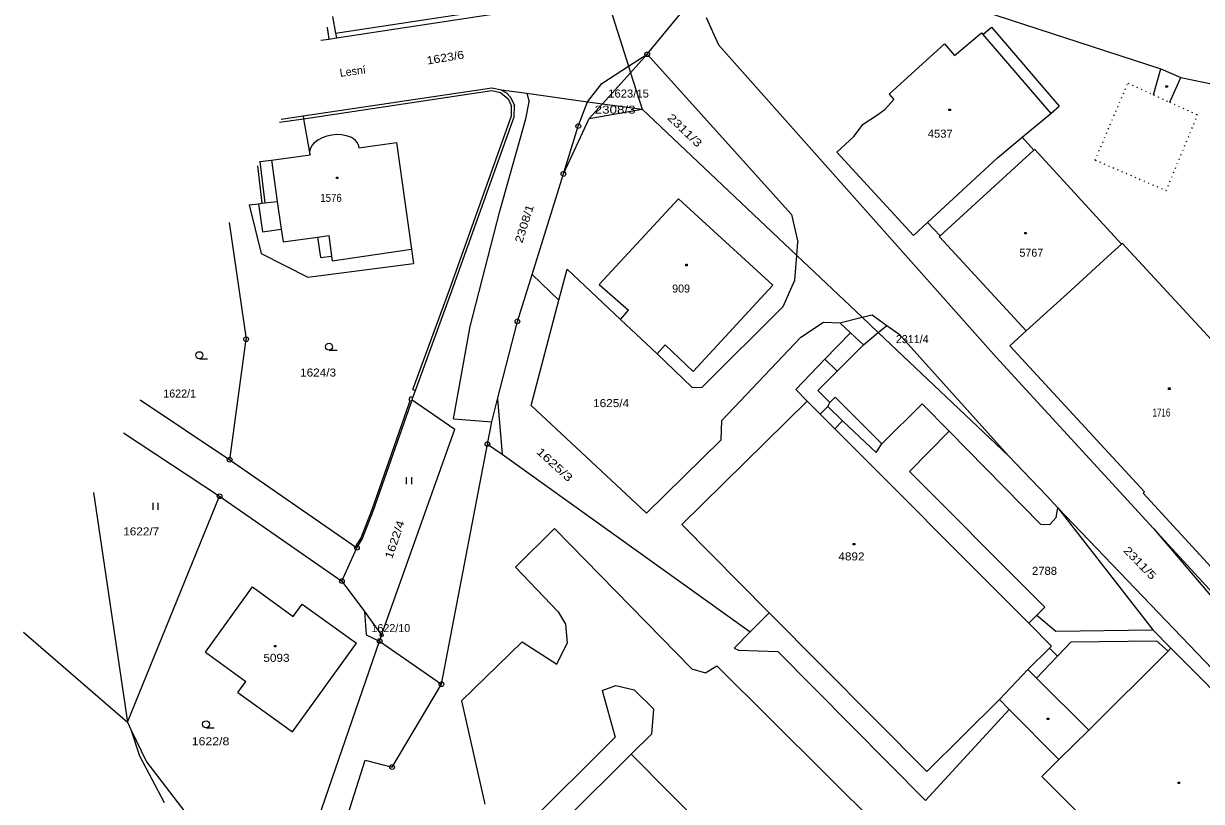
# Model space of a CAD drawing. Extents: x -630464 to -630140, y -1004543 to -1004208.
# Drawn here: x -630464 to -630338.9, y -1004428.9 to -1004346.3 of the extents above; entities that cross this region are included whole.
import ezdxf

# ---------------------------------------------------------------- set-up
doc = ezdxf.new("R2010")
doc.units = 0
doc.header["$LTSCALE"] = 0.34
doc.linetypes.add('DOTTED', pattern=[1.5, 0.3, -1.2])
for name, color, linetype, lineweight in [('1', 7, 'Continuous', 13), ('2', 7, 'Continuous', 13), ('23', 7, 'Continuous', 13), ('25', 7, 'Continuous', 13), ('28', 7, 'Continuous', 13)]:
    doc.layers.add(name, color=color, linetype=linetype, lineweight=lineweight)
for name, color, linetype in [('14', 7, 'Continuous'), ('15', 7, 'Continuous'), ('38', 7, 'Continuous')]:
    doc.layers.add(name, color=color, linetype=linetype)

msp = doc.modelspace()

# ---------------------------------------------------------------- linework, layer by layer
at = {"layer": '1'}
for p, q in [((-630397.75, -1004349.57), (-630393.43, -1004344.32)), ((-630365.09, -1004344), (-630343.21, -1004351.12)), ((-630431.183, -1004345.566), (-630430.87, -1004347.35)), ((-630431.753, -1004346.701), (-630431.75, -1004346.72)), ((-630431.75, -1004346.72), (-630431.57, -1004347.96)), ((-630432.449, -1004348.088), (-630431.57, -1004347.96)), ((-630430.87, -1004347.35), (-630430.78, -1004347.84)), ((-630343.97, -1004353.88), (-630343.21, -1004351.12)), ((-630434.31, -1004356.13), (-630414.28, -1004353.14)), ((-630413.24, -1004353.35), (-630410.54, -1004353.72)), ((-630372.04, -1004353.83), (-630371.55, -1004354.38)), ((-630411.9, -1004356.21), (-630411.87, -1004355.02)), ((-630354.89, -1004355.86), (-630353.98, -1004355.08)), ((-630436.658, -1004356.468), (-630434.31, -1004356.13)), ((-630357.92, -1004358.39), (-630354.89, -1004355.86)), ((-630360.55, -1004360.58), (-630357.92, -1004358.39)), ((-630377.61, -1004359.98), (-630369.46, -1004368.81)), ((-630367.97, -1004367.43), (-630360.55, -1004360.58)), ((-630439.154, -1004361.437), (-630438.69, -1004365.4)), ((-630442.168, -1004367.438), (-630440.37, -1004379.84)), ((-630369.46, -1004368.81), (-630367.97, -1004367.43)), ((-630366.62, -1004368.87), (-630367.97, -1004367.43)), ((-630381.87, -1004370.96), (-630381.75, -1004369.54)), ((-630366.72, -1004368.97), (-630366.62, -1004368.87)), ((-630357.49, -1004378.95), (-630366.72, -1004368.97)), ((-630353.16, -1004375.01), (-630348.44, -1004370.69)), ((-630347.29, -1004369.64), (-630333.06, -1004385.05)), ((-630433.83, -1004373.26), (-630422.58, -1004371.78)), ((-630409.99, -1004372.95), (-630407.15, -1004375.7)), ((-630391.95, -1004384.98), (-630383.32, -1004376.35)), ((-630381.44, -1004379.61), (-630379.02, -1004378.03)), ((-630379.02, -1004378.03), (-630377.29, -1004378.09)), ((-630378.89, -1004381.97), (-630376.15, -1004379.15)), ((-630376.15, -1004379.15), (-630374.77, -1004380.43)), ((-630442.12, -1004392.63), (-630440.37, -1004379.84)), ((-630377.58, -1004383.24), (-630374.77, -1004380.43)), ((-630359.24, -1004380.55), (-630344.92, -1004396.04)), ((-630381.98, -1004385.16), (-630378.89, -1004381.97)), ((-630379.64, -1004385.29), (-630377.58, -1004383.24)), ((-630393.02, -1004384.92), (-630391.95, -1004384.98)), ((-630381.98, -1004385.16), (-630380.76, -1004386.4)), ((-630379.64, -1004385.29), (-630378.37, -1004386.56)), ((-630451.637, -1004386.291), (-630442.12, -1004392.63)), ((-630413.67, -1004386.22), (-630413.18, -1004392.06)), ((-630410.08, -1004386.88), (-630397.83, -1004398.3)), ((-630394.08, -1004399.52), (-630380.76, -1004386.4)), ((-630372.84, -1004390.95), (-630368.56, -1004386.69)), ((-630368.56, -1004386.69), (-630365.69, -1004389.61)), ((-630397.83, -1004398.3), (-630389.92, -1004390.51)), ((-630413.18, -1004392.06), (-630386.82, -1004410.92)), ((-630369.91, -1004393.89), (-630356.72, -1004407.09)), ((-630456.571, -1004396.114), (-630452.97, -1004420.51)), ((-630452.97, -1004420.51), (-630443.2, -1004396.51)), ((-630443.2, -1004396.51), (-630430.19, -1004405.52)), ((-630345.07, -1004396.18), (-630344.92, -1004396.04)), ((-630345.07, -1004396.18), (-630336.65, -1004405.35)), ((-630354.15, -1004397.75), (-630317.27, -1004436.17)), ((-630394.08, -1004399.52), (-630384.8, -1004408.88)), ((-630444.68, -1004413.09), (-630439.71, -1004406.15)), ((-630356.72, -1004407.09), (-630355.52, -1004408.3)), ((-630356.38, -1004409.15), (-630355.52, -1004408.3)), ((-630427.81, -1004408.76), (-630425.98, -1004411.26)), ((-630356.38, -1004409.15), (-630354.36, -1004410.83)), ((-630464.017, -1004410.94), (-630452.97, -1004420.51)), ((-630426.2, -1004411.89), (-630419.62, -1004416.48)), ((-630444.68, -1004413.09), (-630440.39, -1004416.19)), ((-630441.24, -1004417.36), (-630440.39, -1004416.19)), ((-630452.61, -1004421.27), (-630450.96, -1004424.73)), ((-630355.83, -1004426.26), (-630354.04, -1004424.47)), ((-630450.96, -1004424.73), (-630446.52, -1004430.49))]:
    msp.add_line(p, q, dxfattribs=at)
at = {"layer": '1', "linetype": 'DOTTED'}
for p, q in [((-630350.17, -1004360.81), (-630346.69, -1004352.63)), ((-630346.69, -1004352.63), (-630343.97, -1004353.88)), ((-630342.25, -1004354.67), (-630339.29, -1004356.02)), ((-630342.62, -1004364.05), (-630339.29, -1004356.02)), ((-630350.17, -1004360.81), (-630342.62, -1004364.05))]:
    msp.add_line(p, q, dxfattribs=at)
at = {"layer": '1'}
for points in [[(-630431.57, -1004347.96), (-630430.78, -1004347.84), (-630408.36, -1004344.42), (-630404.14, -1004336.97), (-630403.55, -1004338.86), (-630399.75, -1004350.85), (-630399.53, -1004351.54)], [(-630391.49, -1004345.66), (-630390.2, -1004348.57), (-630360.7, -1004381.74)], [(-630372.04, -1004353.83), (-630366.19, -1004348.48), (-630365.1, -1004349.71), (-630362.23, -1004347.31), (-630362.1, -1004347.46), (-630361.19, -1004346.68), (-630353.98, -1004355.08)], [(-630399.53, -1004351.54), (-630397.75, -1004349.57), (-630382.44, -1004366.59), (-630381.75, -1004369.54)], [(-630402.51, -1004354.83), (-630399.53, -1004351.54), (-630398.31, -1004355.4)], [(-630342.25, -1004354.67), (-630341.06, -1004352.03), (-630321.38, -1004356.13)], [(-630414.28, -1004353.14), (-630413.24, -1004353.35), (-630412.7, -1004353.67), (-630412.3, -1004354.13), (-630411.87, -1004355.02)], [(-630410.54, -1004353.72), (-630404.12, -1004354.61), (-630402.51, -1004354.83)], [(-630377.61, -1004359.98), (-630375.82, -1004358.31), (-630374.83, -1004356.99), (-630373.29, -1004356.01), (-630372.49, -1004355.4), (-630371.55, -1004354.38)], [(-630409.99, -1004372.95), (-630406.66, -1004362.29), (-630403.94, -1004356.41), (-630398.31, -1004355.4), (-630381.87, -1004370.96)], [(-630403.94, -1004356.41), (-630402.51, -1004354.83), (-630398.31, -1004355.4)], [(-630434.31, -1004356.13), (-630434.26, -1004356.43), (-630433.63, -1004360)], [(-630422.74, -1004386.27), (-630422.65, -1004386.02), (-630422.39, -1004385.27), (-630418.5, -1004374.7), (-630411.9, -1004356.21)], [(-630428.46, -1004359.16), (-630428.4, -1004359.5), (-630424.41, -1004358.93), (-630422.79, -1004370.29), (-630422.58, -1004371.78)], [(-630347.39, -1004369.73), (-630356.59, -1004359.69), (-630356.69, -1004359.77), (-630357.92, -1004358.39)], [(-630440.04, -1004365.58), (-630439.04, -1004365.45), (-630438.69, -1004365.4)], [(-630440.04, -1004365.58), (-630438.76, -1004370.72), (-630433.83, -1004373.26)], [(-630348.44, -1004370.69), (-630347.39, -1004369.73), (-630347.29, -1004369.64)], [(-630383.32, -1004376.35), (-630382.08, -1004373.55), (-630381.87, -1004370.96), (-630374.93, -1004377.51)], [(-630413.67, -1004386.22), (-630411.55, -1004377.94), (-630409.99, -1004372.95)], [(-630410.08, -1004386.88), (-630407.15, -1004375.7), (-630406.28, -1004372.4), (-630400.61, -1004377.74), (-630396.71, -1004381.39), (-630393.02, -1004384.92)], [(-630359.24, -1004380.55), (-630357.49, -1004378.95), (-630353.16, -1004375.01)], [(-630377.29, -1004378.09), (-630374.93, -1004377.51), (-630373.22, -1004379.14), (-630359.37, -1004392.23), (-630355.39, -1004396.39), (-630354.15, -1004397.75)], [(-630374.93, -1004377.51), (-630373.85, -1004377.25), (-630372.29, -1004378.37), (-630370.98, -1004379.31), (-630359.37, -1004392.23)], [(-630389.92, -1004390.51), (-630389.85, -1004388.46), (-630381.44, -1004379.61)], [(-630360.7, -1004381.74), (-630343.98, -1004399.94), (-630338.03, -1004406.42), (-630333.23, -1004411.18), (-630324.32, -1004420.02), (-630324.04, -1004420.28), (-630303.74, -1004439.53), (-630293.73, -1004449.03), (-630288.99, -1004453.52), (-630254.82, -1004485.91)], [(-630430.19, -1004405.52), (-630428.6, -1004401.98), (-630428.05, -1004401.07), (-630426.83, -1004397.99), (-630422.89, -1004386.7), (-630422.74, -1004386.27), (-630418.21, -1004389.39)], [(-630378.37, -1004386.56), (-630377.79, -1004385.98), (-630372.84, -1004390.95)], [(-630426.2, -1004411.89), (-630425.98, -1004411.26), (-630418.21, -1004389.39)], [(-630369.91, -1004393.89), (-630365.69, -1004389.61), (-630355.97, -1004399.47)], [(-630419.62, -1004416.48), (-630414.74, -1004390.98), (-630413.18, -1004392.06)], [(-630442.12, -1004392.63), (-630428.74, -1004401.88), (-630428.6, -1004401.98)], [(-630355.97, -1004399.47), (-630355, -1004399.5), (-630354.31, -1004398.78), (-630354.15, -1004397.75), (-630344.06, -1004410.7)], [(-630430.19, -1004405.52), (-630427.81, -1004408.76), (-630427.62, -1004411.24), (-630426.2, -1004411.89)], [(-630439.71, -1004406.15), (-630435.37, -1004409.29), (-630434.42, -1004407.97), (-630428.66, -1004412.13)], [(-630388.51, -1004412.66), (-630386.82, -1004410.92), (-630384.8, -1004408.88)], [(-630354.36, -1004410.83), (-630344.06, -1004410.7), (-630342.12, -1004412.66), (-630334.14, -1004420.69), (-630328.57, -1004426.3)], [(-630453.27, -1004473.63), (-630434.6, -1004435.86), (-630434.12, -1004434.9), (-630426.2, -1004411.89)], [(-630441.24, -1004417.36), (-630435.45, -1004421.54), (-630428.66, -1004412.13)], [(-630388.51, -1004412.66), (-630388.08, -1004412.86), (-630383.88, -1004413), (-630368.18, -1004428.81)], [(-630450.67, -1004475.56), (-630431.15, -1004435.38), (-630427.72, -1004424.53), (-630424.86, -1004425.28), (-630419.62, -1004416.48)], [(-630368.18, -1004428.81), (-630359.29, -1004419.16), (-630354.04, -1004424.47)], [(-630452.97, -1004420.51), (-630452.61, -1004421.27), (-630451.7, -1004424.09), (-630449.09, -1004429.04)], [(-630414.09, -1004438.44), (-630413.36, -1004437.72), (-630399.48, -1004423.9), (-630390.92, -1004432.51)], [(-630355.83, -1004426.26), (-630342.18, -1004439.92), (-630329.96, -1004427.73), (-630329.26, -1004426.99), (-630328.44, -1004427.8), (-630326.87, -1004429.52), (-630322.01, -1004434.84)]]:
    msp.add_lwpolyline(points, dxfattribs=at)
for centre, radius, start, end in [((-630430.724, -1004361.937), 3.827, 66.37961, 130.12116), ((-630432.222, -1004360.033), 1.408, 133.41474, 178.66028), ((-630429.79, -1004359.76), 1.459, 24.2739, 65.7261)]:
    msp.add_arc(centre, radius, start, end, dxfattribs=at)
at = {"layer": '2'}
for p, q in [((-630430.87, -1004347.35), (-630408.67, -1004343.96)), ((-630431.763, -1004346.722), (-630431.75, -1004346.72)), ((-630362.1, -1004347.46), (-630354.89, -1004355.86)), ((-630399.75, -1004350.85), (-630397.75, -1004349.57)), ((-630402.59, -1004352.67), (-630399.75, -1004350.85)), ((-630343.21, -1004351.12), (-630341.06, -1004352.03)), ((-630434.26, -1004356.43), (-630414.27, -1004353.44)), ((-630414.27, -1004353.44), (-630413.36, -1004353.63)), ((-630413.36, -1004353.63), (-630412.55, -1004354.3)), ((-630412.55, -1004354.3), (-630412.17, -1004355.08)), ((-630410.54, -1004353.72), (-630410.29, -1004354.61)), ((-630412.19, -1004356.1), (-630412.17, -1004355.08)), ((-630410.67, -1004356.44), (-630410.29, -1004354.61)), ((-630436.824, -1004356.798), (-630434.26, -1004356.43)), ((-630418.78, -1004374.6), (-630412.19, -1004356.1)), ((-630413.41, -1004366.24), (-630410.67, -1004356.44)), ((-630406.66, -1004362.29), (-630405.08, -1004357.21)), ((-630438.9, -1004360.98), (-630437.68, -1004360.82)), ((-630437.68, -1004360.82), (-630433.58, -1004360.27)), ((-630437.68, -1004360.82), (-630437.06, -1004365.2)), ((-630433.63, -1004360), (-630433.58, -1004360.27)), ((-630366.62, -1004368.87), (-630356.69, -1004359.77)), ((-630438.905, -1004360.941), (-630438.9, -1004360.98)), ((-630438.9, -1004360.98), (-630438.39, -1004365.37)), ((-630439.04, -1004365.45), (-630438.62, -1004368.44)), ((-630438.69, -1004365.4), (-630438.39, -1004365.37)), ((-630438.39, -1004365.37), (-630437.06, -1004365.2)), ((-630437.06, -1004365.2), (-630436.64, -1004368.16)), ((-630402.85, -1004374.01), (-630394.42, -1004364.92)), ((-630394.42, -1004364.92), (-630384.4, -1004374.1)), ((-630416.58, -1004378.5), (-630413.41, -1004366.24)), ((-630438.62, -1004368.44), (-630436.64, -1004368.16)), ((-630432.79, -1004368.99), (-630431.6, -1004368.82)), ((-630432.79, -1004368.99), (-630432.48, -1004371.17)), ((-630432.48, -1004371.17), (-630431.29, -1004371)), ((-630402.85, -1004374.01), (-630399.75, -1004376.76)), ((-630392.89, -1004383.25), (-630384.4, -1004374.1)), ((-630422.67, -1004385.17), (-630418.78, -1004374.6)), ((-630400.61, -1004377.74), (-630399.75, -1004376.76)), ((-630377.29, -1004378.09), (-630376.15, -1004379.15)), ((-630418.33, -1004388.3), (-630416.58, -1004378.5)), ((-630374.77, -1004380.43), (-630373.22, -1004379.14)), ((-630373.22, -1004379.14), (-630372.29, -1004378.37)), ((-630378.89, -1004381.97), (-630377.58, -1004383.24)), ((-630422.67, -1004385.17), (-630422.39, -1004385.27)), ((-630426.99, -1004397.92), (-630423.05, -1004386.65)), ((-630423.06, -1004386.31), (-630422.93, -1004385.92)), ((-630423.06, -1004386.31), (-630422.95, -1004386.36)), ((-630423.05, -1004386.65), (-630422.95, -1004386.36)), ((-630422.93, -1004385.92), (-630422.65, -1004386.02)), ((-630414.28, -1004388.6), (-630413.67, -1004386.22)), ((-630380.76, -1004386.4), (-630379.49, -1004387.68)), ((-630378.57, -1004387), (-630378.37, -1004386.56)), ((-630378.57, -1004387), (-630377, -1004388.5)), ((-630418.33, -1004388.3), (-630414.28, -1004388.6)), ((-630379.37, -1004387.8), (-630377.84, -1004389.34)), ((-630414.74, -1004390.98), (-630414.28, -1004388.6)), ((-630377.84, -1004389.34), (-630377, -1004388.5)), ((-630377.84, -1004389.34), (-630358.42, -1004408.79)), ((-630377, -1004388.5), (-630373.45, -1004391.88)), ((-630453.391, -1004389.783), (-630443.2, -1004396.51)), ((-630373.45, -1004391.88), (-630372.84, -1004390.95)), ((-630428.2, -1004400.99), (-630426.99, -1004397.92)), ((-630411.77, -1004404.03), (-630407.62, -1004399.93)), ((-630407.62, -1004399.93), (-630393.02, -1004414.85)), ((-630343.98, -1004399.94), (-630333.94, -1004411.74)), ((-630428.74, -1004401.88), (-630428.2, -1004400.99)), ((-630411.77, -1004404.03), (-630407.21, -1004408.78)), ((-630407.21, -1004408.78), (-630406.44, -1004410.11)), ((-630384.8, -1004408.88), (-630368.06, -1004425.76)), ((-630358.42, -1004408.79), (-630357.5, -1004409.71)), ((-630357.22, -1004410), (-630356.38, -1004409.15)), ((-630406.44, -1004410.11), (-630406.27, -1004412.13)), ((-630357.5, -1004409.71), (-630357.22, -1004410)), ((-630357.22, -1004410), (-630354.81, -1004412.42)), ((-630417.48, -1004418.25), (-630411.04, -1004411.98)), ((-630411.04, -1004411.98), (-630407.35, -1004414.34)), ((-630407.35, -1004414.34), (-630406.27, -1004412.13)), ((-630354.17, -1004413.49), (-630352.71, -1004411.96)), ((-630352.71, -1004411.96), (-630343.64, -1004411.86)), ((-630343.64, -1004411.86), (-630342.41, -1004412.98)), ((-630357.31, -1004414.92), (-630355.03, -1004412.64)), ((-630355.03, -1004412.64), (-630354.81, -1004412.42)), ((-630355.03, -1004412.64), (-630354.17, -1004413.49)), ((-630350.86, -1004421.35), (-630342.41, -1004412.98)), ((-630342.41, -1004412.98), (-630342.12, -1004412.66)), ((-630391.58, -1004415.26), (-630390.36, -1004414.51)), ((-630390.36, -1004414.51), (-630367.74, -1004436.99)), ((-630356.41, -1004415.82), (-630354.17, -1004413.49)), ((-630393.02, -1004414.85), (-630391.58, -1004415.26)), ((-630360.33, -1004418.11), (-630357.31, -1004414.92)), ((-630357.31, -1004414.92), (-630356.41, -1004415.82)), ((-630356.41, -1004415.82), (-630350.86, -1004421.35)), ((-630402.55, -1004417.14), (-630401.11, -1004416.6)), ((-630401.11, -1004416.6), (-630399.15, -1004417.06)), ((-630399.15, -1004417.06), (-630397.07, -1004419.14)), ((-630417.48, -1004418.25), (-630415.01, -1004429.22)), ((-630402.55, -1004417.14), (-630401.16, -1004422.1)), ((-630368.06, -1004425.76), (-630360.33, -1004418.11)), ((-630360.33, -1004418.11), (-630359.29, -1004419.16)), ((-630397.28, -1004421.76), (-630397.07, -1004419.14)), ((-630411.76, -1004432.63), (-630401.16, -1004422.1)), ((-630399.48, -1004423.9), (-630397.28, -1004421.76)), ((-630354.04, -1004424.47), (-630350.86, -1004421.35))]:
    msp.add_line(p, q, dxfattribs=at)
at = {"layer": '2', "linetype": 'DOTTED'}
msp.add_line((-630343.97, -1004353.88), (-630342.25, -1004354.67), dxfattribs=at)
at = {"layer": '2'}
for points in [[(-630405.08, -1004357.21), (-630404.12, -1004354.61), (-630402.59, -1004352.67)], [(-630436.64, -1004368.16), (-630436.44, -1004369.51), (-630432.79, -1004368.99)], [(-630431.6, -1004368.82), (-630431.29, -1004371), (-630431.22, -1004371.5), (-630422.79, -1004370.29)], [(-630396.71, -1004381.39), (-630395.87, -1004380.42), (-630392.89, -1004383.25)], [(-630379.49, -1004387.68), (-630379.37, -1004387.8), (-630378.57, -1004387)]]:
    msp.add_lwpolyline(points, dxfattribs=at)
at = {"layer": '23'}
for p, q in [((-630445.34, -1004381.91), (-630444.465, -1004381.91)), ((-630431.56, -1004381.01), (-630430.685, -1004381.01)), ((-630423.32, -1004395.23), (-630423.32, -1004394.48)), ((-630422.82, -1004394.48), (-630422.82, -1004395.23)), ((-630450.25, -1004397.97), (-630450.25, -1004397.22)), ((-630449.75, -1004397.22), (-630449.75, -1004397.97)), ((-630444.63, -1004421.11), (-630443.755, -1004421.11))]:
    msp.add_line(p, q, dxfattribs=at)
for centre in [(-630431.56, -1004380.635), (-630445.34, -1004381.535), (-630444.63, -1004420.735)]:
    msp.add_circle(centre, 0.375, dxfattribs=at)
at = {"layer": '25'}
for points in [[(-630342.65, -1004352.93), (-630342.5, -1004352.93), (-630342.5, -1004353.08), (-630342.65, -1004353.08)], [(-630365.7, -1004355.39), (-630365.55, -1004355.39), (-630365.55, -1004355.54), (-630365.7, -1004355.54)], [(-630430.77, -1004362.61), (-630430.62, -1004362.61), (-630430.62, -1004362.76), (-630430.77, -1004362.76)], [(-630357.64, -1004368.5), (-630357.49, -1004368.5), (-630357.49, -1004368.65), (-630357.64, -1004368.65)], [(-630393.67, -1004371.88), (-630393.52, -1004371.88), (-630393.52, -1004372.03), (-630393.67, -1004372.03)], [(-630342.37, -1004385.01), (-630342.22, -1004385.01), (-630342.22, -1004385.16), (-630342.37, -1004385.16)], [(-630375.87, -1004401.52), (-630375.72, -1004401.52), (-630375.72, -1004401.67), (-630375.87, -1004401.67)], [(-630437.35, -1004412.36), (-630437.2, -1004412.36), (-630437.2, -1004412.51), (-630437.35, -1004412.51)], [(-630355.26, -1004420.09), (-630355.11, -1004420.09), (-630355.11, -1004420.24), (-630355.26, -1004420.24)], [(-630341.37, -1004426.87), (-630341.22, -1004426.87), (-630341.22, -1004427.02), (-630341.37, -1004427.02)]]:
    msp.add_lwpolyline(points, close=True, dxfattribs=at)
at = {"layer": '28'}
for centre, radius in [((-630397.75, -1004349.57), 0.25), ((-630397.75, -1004349.57), 0.005), ((-630405.08, -1004357.21), 0.25), ((-630405.08, -1004357.21), 0.005), ((-630406.66, -1004362.29), 0.25), ((-630406.66, -1004362.29), 0.005), ((-630411.55, -1004377.94), 0.25), ((-630411.55, -1004377.94), 0.005), ((-630440.37, -1004379.84), 0.25), ((-630440.37, -1004379.84), 0.005), ((-630414.74, -1004390.98), 0.25), ((-630414.74, -1004390.98), 0.005), ((-630442.12, -1004392.63), 0.25), ((-630442.12, -1004392.63), 0.005), ((-630443.2, -1004396.51), 0.25), ((-630443.2, -1004396.51), 0.005), ((-630428.6, -1004401.98), 0.25), ((-630428.6, -1004401.98), 0.005), ((-630430.19, -1004405.52), 0.25), ((-630430.19, -1004405.52), 0.005), ((-630426.2, -1004411.89), 0.25), ((-630426.2, -1004411.89), 0.005), ((-630425.98, -1004411.26), 0.168), ((-630425.98, -1004411.26), 0.00335), ((-630419.62, -1004416.48), 0.25), ((-630419.62, -1004416.48), 0.005), ((-630424.86, -1004425.28), 0.25), ((-630424.86, -1004425.28), 0.005)]:
    msp.add_circle(centre, radius, dxfattribs=at)

# ---------------------------------------------------------------- texts
at = {"layer": '14'}
for s, rotation, width, p in [('1623/6', 9.463, 1.15, (-630421.11, -1004350.67)), ('2311/3', 316.31, 1.3, (-630395.7, -1004356.4)), ('2308/1', 72.583, 1.2, (-630411.04, -1004369.69)), ('1625/3', 317.556, 1.35, (-630409.61, -1004391.88)), ('1622/4', 71.365, 1.2, (-630424.86, -1004403.23)), ('2311/5', 314.23, 1.25, (-630347.23, -1004402.34))]:
    msp.add_text(s, height=0.85, rotation=rotation, dxfattribs=dict(at, width=width)).set_placement(p)
for s, width, p in [('1623/15', 1.05, (-630401.9, -1004354.17)), ('2308/3', 1.25, (-630403.34, -1004355.88)), ('1624/3', 1.1, (-630434.64, -1004383.8)), ('1625/4', 1.1, (-630403.51, -1004387.05)), ('1622/7', 1.1, (-630453.43, -1004400.67)), ('2788', 1.05, (-630356.88, -1004404.86)), ('1622/8', 1.15, (-630446.15, -1004422.96))]:
    msp.add_text(s, height=0.85, dxfattribs=dict(at, width=width)).set_placement(p)
for s, p in [('2311/4', (-630371.34, -1004380.25)), ('1622/1', (-630449.17, -1004386.03)), ('1622/10', (-630427.05, -1004410.94))]:
    msp.add_text(s, height=0.85, dxfattribs=at).set_placement(p)
at = {"layer": '15'}
for s, width, p in [('4537', 1.05, (-630367.96, -1004358.43)), ('1576', 0.9, (-630432.49, -1004365.25)), ('1716', 0.75, (-630344.08, -1004388.05)), ('4892', 1.1, (-630377.45, -1004403.33)), ('5093', 1.1, (-630438.54, -1004414.1))]:
    msp.add_text(s, height=0.85, dxfattribs=dict(at, width=width)).set_placement(p)
for s, p in [('5767', (-630358.216, -1004371.08)), ('909', (-630395.11, -1004374.88))]:
    msp.add_text(s, height=0.85, dxfattribs=at).set_placement(p)
at = {"layer": '38'}
msp.add_text('Lesní', height=0.85, rotation=7.63, dxfattribs=at).set_placement((-630430.37, -1004351.98))

doc.saveas('drawing.dxf')
